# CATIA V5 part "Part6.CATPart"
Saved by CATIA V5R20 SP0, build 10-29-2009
Part number: 1bola238
Revision: ANY
Definition: UNKNOWN
Nomenclature: 1bola238
Source: Unknown
Bounding box of the stored display mesh (mm): x -1.19 to 1.19, y -1.19 to 1.19, z -1.19 to 1.19
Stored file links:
  C:\Users\Utente\Desktop\IO LAVORO\3D X SITO CF\CUMSA\3D files BA\BA 081620\Part6.CATPart
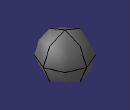
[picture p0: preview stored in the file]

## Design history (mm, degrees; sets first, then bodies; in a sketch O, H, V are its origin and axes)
Body1 "Revolución1" (main body)
  Solid1: solid without history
